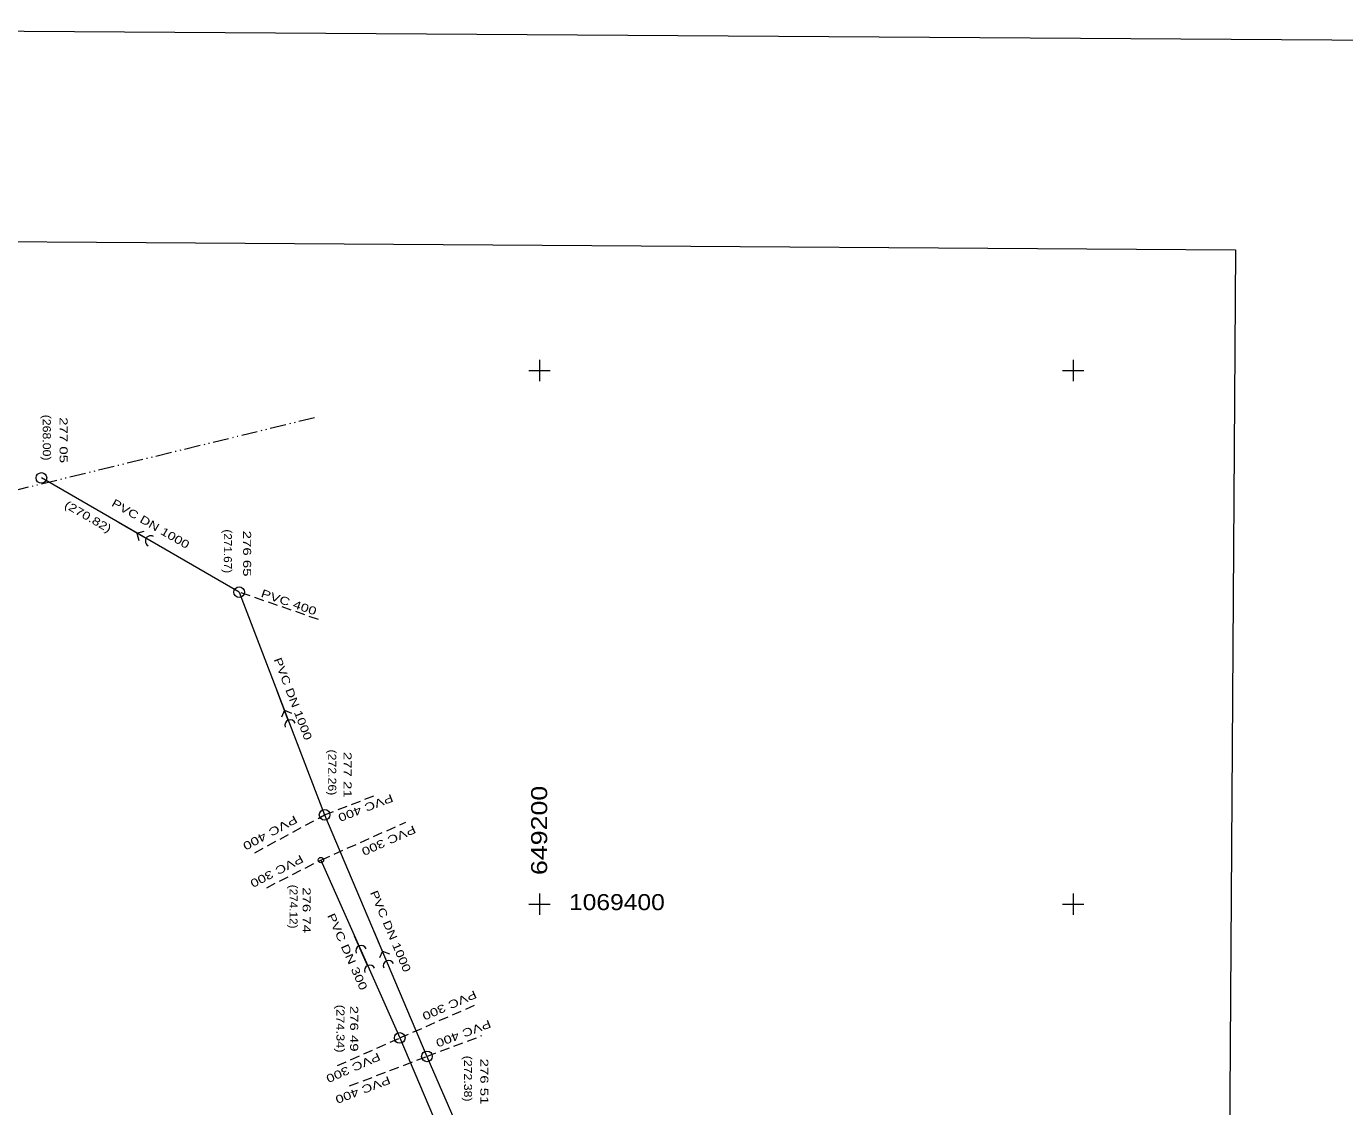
# Model space of a CAD drawing. Extents: x -649434 to -648798, y -1070102 to -1069235.
# Drawn here: x -649296.2 to -649049.1, y -1069438 to -1069235.5 of the extents above; entities that cross this region are included whole.
import ezdxf
from ezdxf.enums import TextEntityAlignment as Align

# ---------------------------------------------------------------- set-up
doc = ezdxf.new("R2010")
doc.units = 0
doc.header["$LTSCALE"] = 0.6
doc.linetypes.add('DASH_DOUBLE_DOT', pattern=[9.2, 5, -1.2, 0.3, -1.2, 0.3, -1.2])
doc.linetypes.add('MEDIUM_DASHED', pattern=[4.5, 3, -1.5])
for name, color, linetype in [('19', 7, 'Continuous'), ('3', 7, 'Continuous'), ('4', 7, 'Continuous')]:
    doc.layers.add(name, color=color, linetype=linetype)
for name, color, linetype, lineweight in [('27', 7, 'Continuous', 13), ('36', 7, 'Continuous', 13), ('40', 7, 'Continuous', 13), ('50', 7, 'MEDIUM_DASHED', 13), ('51', 7, 'MEDIUM_DASHED', 13), ('60', 7, 'Continuous', 13), ('61', 7, 'Continuous', 13), ('62', 7, 'Continuous', 13), ('63', 7, 'Continuous', 13)]:
    doc.layers.add(name, color=color, linetype=linetype, lineweight=lineweight)

msp = doc.modelspace()

# ---------------------------------------------------------------- linework, layer by layer
at = {"layer": '27'}
for centre, radius in [((-649293.36, -1069320.13), 1), ((-649256.3, -1069341.53), 1), ((-649240.28, -1069383.27), 1), ((-649240.98, -1069391.74), 0.5), ((-649226.21, -1069425.1), 1), ((-649221.1, -1069428.54), 1)]:
    msp.add_circle(centre, radius, dxfattribs=at)
at = {"layer": '36', "linetype": 'DASH_DOUBLE_DOT'}
msp.add_line((-649242.18, -1069308.86), (-649355.3, -1069336.33), dxfattribs=at)
at = {"layer": '36'}
msp.add_line((-649256.3, -1069341.53), (-649293.36, -1069320.13), dxfattribs=at)
msp.add_lwpolyline([(-649256.3, -1069341.53), (-649240.28, -1069383.27), (-649221.1, -1069428.54), (-649201.15, -1069474.5), (-649181.05, -1069521.05), (-649161.63, -1069566.58), (-649142.48, -1069611.79), (-649122.43, -1069658.25), (-649109.25, -1069689.61), (-649102.53, -1069705.01), (-649082.85, -1069750.86), (-649061.09, -1069796.01), (-649037.43, -1069838.84), (-649009.95, -1069880.28), (-648980.08, -1069920.53), (-648948.81, -1069960.67), (-648918.35, -1070000.17)], dxfattribs=at)
at = {"layer": '40'}
msp.add_lwpolyline([(-649240.98, -1069391.74), (-649226.21, -1069425.1), (-649206.21, -1069472.2), (-649186.23, -1069518.73), (-649166.76, -1069564.43), (-649147.48, -1069609.76), (-649127.44, -1069656.48), (-649107.92, -1069702.15), (-649088.16, -1069748.28), (-649066.33, -1069793.84), (-649042.6, -1069837.07), (-649015.72, -1069878.6), (-648986.38, -1069919.27)], dxfattribs=at)
at = {"layer": '50'}
for points in [[(-649251.13, -1069396.93), (-649240.98, -1069391.74), (-649225.04, -1069384.64)], [(-649237.88, -1069430.27), (-649226.21, -1069425.1), (-649212.03, -1069418.89)]]:
    msp.add_lwpolyline(points, dxfattribs=at)
at = {"layer": '51'}
msp.add_line((-649241.45, -1069346.66), (-649256.3, -1069341.53), dxfattribs=at)
for points in [[(-649253.39, -1069390.38), (-649240.28, -1069383.27), (-649230.47, -1069379.5)], [(-649235.6, -1069434.09), (-649221.1, -1069428.54), (-649210.82, -1069424.66)]]:
    msp.add_lwpolyline(points, dxfattribs=at)
at = {"layer": '60'}
for p, q in [((-649273.735, -1069331.462), (-649278.931, -1069328.462)), ((-649275.467, -1069330.462), (-649274.101, -1069330.096)), ((-649275.467, -1069330.462), (-649275.101, -1069331.828)), ((-649247.089, -1069365.53), (-649249.239, -1069359.928)), ((-649247.805, -1069363.662), (-649248.381, -1069364.954)), ((-649247.805, -1069363.662), (-649246.514, -1069364.238)), ((-649228.685, -1069410.638), (-649231.025, -1069405.113)), ((-649229.465, -1069408.796), (-649229.996, -1069410.107)), ((-649229.465, -1069408.796), (-649228.154, -1069409.327))]:
    msp.add_line(p, q, dxfattribs=at)
for centre, start, end in [((-649272.8688, -1069331.9625), 59.99606, 239.99606), ((-649246.7305, -1069366.4632), 20.99703, 200.99703), ((-649228.2946, -1069411.5588), 22.96141, 202.96141)]:
    msp.add_arc(centre, 1, start, end, dxfattribs=at)
at = {"layer": '61'}
for p, q in [((-649200, -1069298), (-649200, -1069302)), ((-649100, -1069298), (-649100, -1069302)), ((-649202, -1069300), (-649198, -1069300)), ((-649102, -1069300), (-649098, -1069300)), ((-649200, -1069398), (-649200, -1069402)), ((-649100, -1069398), (-649100, -1069402)), ((-649202, -1069400), (-649198, -1069400)), ((-649102, -1069400), (-649098, -1069400)), ((-649232.227, -1069411.509), (-649234.656, -1069406.023))]:
    msp.add_line(p, q, dxfattribs=at)
for centre in [(-649233.4419, -1069408.7657), (-649231.8226, -1069412.4233)]:
    msp.add_arc(centre, 1, 23.88117, 203.88116, dxfattribs=at)
at = {"layer": '62'}
msp.add_lwpolyline([(-648834.675, -1069239.477), (-648840.315, -1070079.458), (-649434.302, -1070075.471), (-649428.662, -1069235.487)], close=True, dxfattribs=at)
at = {"layer": '63'}
msp.add_lwpolyline([(-649069.599, -1069277.37), (-649072.419, -1069697.36), (-649369.412, -1069695.366), (-649366.592, -1069275.376)], close=True, dxfattribs=at)

# ---------------------------------------------------------------- texts
at = {"layer": '19'}
for s, rotation, width, p in [('PVC 400', 340.942, 1.35, (-649247.2249, -1069344.1355)), ('PVC 400', 201.022, 1.35, (-649232.859, -1069381.2678)), ('PVC 400', 208.472, 1.4, (-649250.8504, -1069385.9901)), ('PVC 300', 204.009, 1.35, (-649228.5708, -1069387.4059)), ('PVC 300', 207.082, 1.35, (-649249.5776, -1069393.1739)), ('PVC 300', 203.651, 1.35, (-649217.1766, -1069418.2994)), ('PVC 400', 200.678, 1.35, (-649214.5337, -1069423.5624)), ('PVC 300', 203.894, 1.35, (-649235.2197, -1069429.9882)), ('PVC 400', 200.945, 1.35, (-649233.3769, -1069434.1254))]:
    msp.add_text(s, height=1.5, rotation=rotation, dxfattribs=dict(at, width=width)).set_placement(p, align=Align.CENTER)
at = {"layer": '3', "width": 1.4}
for s, p in [('277 05 ', (-649289.952, -1069313.427)), ('276 65 ', (-649255.556, -1069334.701)), ('277 21 ', (-649236.731, -1069376.165)), ('276 74 ', (-649244.405, -1069401.526)), ('276 49 ', (-649235.495, -1069423.744)), ('276 51 ', (-649211.104, -1069433.647))]:
    msp.add_text(s, height=1.5, rotation=270, dxfattribs=at).set_placement(p, align=Align.CENTER)
at = {"layer": '36', "width": 1.3}
for rotation, p in [(329.996, (-649273.26, -1069329.3751)), (290.997, (-649246.9186, -1069361.7918)), (292.961, (-649228.617, -1069405.3819))]:
    msp.add_text('PVC DN 1000', height=1.5, rotation=rotation, dxfattribs=at).set_placement(p, align=Align.CENTER)
at = {"layer": '4'}
for s, rotation, width, p in [('(268.00)', 270, 1.15, (-649293.103, -1069312.5685)), ('(270.82)', 329.996, 1.3, (-649285.005, -1069328.0211)), ('(271.67)', 270, 1.1, (-649259.17, -1069333.872)), ('(272.26)', 270, 1.15, (-649239.606, -1069375.324)), ('(274.12)', 270, 1.1, (-649246.862, -1069400.4775)), ('(274.34)', 270, 1.2, (-649238.062, -1069423.3515)), ('(272.38)', 270, 1.15, (-649214.161, -1069432.7135))]:
    msp.add_text(s, height=1.5, rotation=rotation, dxfattribs=dict(at, width=width)).set_placement(p, align=Align.CENTER)
at = {"layer": '40', "width": 1.35}
msp.add_text('PVC DN 300', height=1.5, rotation=293.881, dxfattribs=at).set_placement((-649236.7122, -1069409.2244), align=Align.CENTER)
at = {"layer": '61', "width": 1.25}
msp.add_text('649200', height=3, rotation=90, dxfattribs=at).set_placement((-649198.584, -1069394.562))
at = {"layer": '61', "width": 1.15}
msp.add_text('1069400', height=3, dxfattribs=at).set_placement((-649194.489, -1069401.135))

doc.saveas('drawing.dxf')
